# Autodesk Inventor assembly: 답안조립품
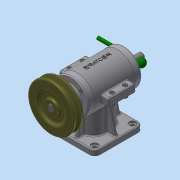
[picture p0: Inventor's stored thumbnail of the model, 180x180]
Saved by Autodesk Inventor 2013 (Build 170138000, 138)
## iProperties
Created: 2015-12
Part Number: 답안조립품
Document SubType Name: Assembly
Designer: Administrator
Mass: 1960.55 g
Surface Area: 1487.03 cm^2
Volume: 472.445 cm^3
Density: 4.14979 g/cm^3
Author: Administrator
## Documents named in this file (19)
- C:\Users\Administrator\Desktop\351208V1032\답안조립품.iam
- C:\Users\Administrator\Desktop\351208V1032\본체.ipt
- C:\Users\Administrator\Desktop\351208V1032\V-벨트풀리.ipt
- C:\Users\Administrator\Desktop\351208V1032\너트 M4.ipt
- C:\Users\Administrator\Desktop\351208V1032\뒤커버.ipt
- C:\Users\Administrator\Desktop\351208V1032\레바.ipt
- C:\Users\Administrator\Desktop\351208V1032\멈춤나사 M3x8.ipt
- C:\Users\Administrator\Desktop\351208V1032\베어링 6201.ipt
- C:\Users\Administrator\Desktop\351208V1032\베어링 6202.ipt
- C:\Users\Administrator\Desktop\351208V1032\본체커버.ipt
- C:\Users\Administrator\Desktop\351208V1032\볼트 M3x0.5x8.ipt
- C:\Users\Administrator\Desktop\351208V1032\볼트 M4 x 16.ipt
- C:\Users\Administrator\Desktop\351208V1032\스프링.ipt
- C:\Users\Administrator\Desktop\351208V1032\슬라이드.ipt
- C:\Users\Administrator\Desktop\351208V1032\앞커버.ipt
- C:\Users\Administrator\Desktop\351208V1032\오일실 12 22 7.ipt
- C:\Users\Administrator\Desktop\351208V1032\와셔 ST 4-100.ipt
- C:\Users\Administrator\Desktop\351208V1032\키 4 x 4 x 18.ipt
- C:\Users\Administrator\Desktop\351208V1032\편심축.ipt
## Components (13 placed, 4 different names)
1. V-벨트풀리:1 — 플러쉬:1
2. ISO 4032 M4:1
3. ISO 4762 M4 x 16:1
4. ISO 7091 ST 4 - 100 HV:1
5. ISO 4762 M4 x 16:2
6. ISO 4762 M4 x 16:3
7. ISO 4762 M4 x 16:4
8. ISO 7091 ST 4 - 100 HV:2
9. ISO 7091 ST 4 - 100 HV:3
10. ISO 7091 ST 4 - 100 HV:4
11. ISO 4032 M4:2
12. ISO 4032 M4:3
13. ISO 4032 M4:4
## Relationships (1: Flush 1)
- 플러쉬:1 [Flush]: V-벨트풀리:1
